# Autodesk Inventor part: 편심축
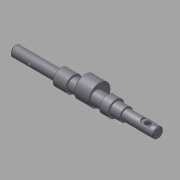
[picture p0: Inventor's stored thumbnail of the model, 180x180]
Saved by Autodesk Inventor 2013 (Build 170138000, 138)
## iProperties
Company: 한국ATC센터
Created: 2015-12
Part Number: 편심축
Document SubType Name: Modeling
Designer: mdu
Density: 7.86 g/cm^3
Mass: 248.518 g
Surface Area: 94.9944 cm^2
Volume: 31.6181 cm^3
Material: 강철, 연강
Author: mdu
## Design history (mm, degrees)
sketch "스케치1"
  geometry: L1 (-84.5, 0)-(84.5, 0); L2 (-84.5, 0)-(-84.5, 6); L3 (-84.5, 6)-(-30.5, 6); L4 (-30.5, 6)-(-30.5, 9.5); L5 (-30.5, 9.5)-(-15.5, 9.5); L6 (-15.5, 9.5)-(-15.5, 7.5); L7 (-15.5, 7.5)-(46.5, 7.5); L8 (84.5, 6)-(84.5, 0); L9 (34.5, 7.5)-(34.5, 9.5); L10 (34.5, 9.5)-(24.5, 9.5); L11 (24.5, 9.5)-(24.5, 7.5); L12 (46.5, 7.5)-(46.5, 6); L13 (46.5, 6)-(84.5, 6); 2 further points
  constraints: 26 end point, 6 parallel, 6 perpendicular, 2 point on line, 1 coincident, 1 horizontal, 1 midpoint
  dimensions: "d1" = 12 diameter of L3 L1; "d2" = 15 diameter of L7 L1; "d4" = 15 distance of L4.end L5.end; "d5" = 19 diameter of L5 L1; "d24" = 10 distance of L9.end L10.end; "d25" = 19 diameter of L10 L1; "d27" = 40 distance between parallel lines of L11 L6; "d28" = 54 distance of L2.end L3.end; "d29" = 50 distance between parallel lines of L8 L9; "d41" = 38 distance between parallel lines of L8 L12; "d42" = 12 diameter of L13 L1
revolve "회전1" stored, may be unused: angle "d6" = 90 deg
node "작업 평면1"
sketch "스케치2"
  geometry: C1 r 7.5 at (0, 0) reference; C2 r 12.5 at (0, 4.5); 1 further point
  constraints: 1 centre point, 1 vertical alignment
  dimensions: "d8" = 4.5 distance of point (0, 0) C2.centre; "d9" = 25 diameter of C2
extrude "돌출1" join sketch "스케치2" distance "d10" = 18; taper "d11" = 0 deg
chamfer "모따기1" distance "d12" = 1; stored, may be unused: second distance "d13" = 2, angle "d14" = 45 deg
chamfer "모따기2" distance "d15" = 0.5; stored, may be unused: second distance "d16" = 2, angle "d17" = 45 deg
node "작업 평면2"
sketch "스케치3"
  geometry: L1 (4, -2)-(18, -2); L2 (18, 2)-(4, 2); L3 (27, 5)-(27, -5) reference; A1 r 2 centre (18, 0) between (18, -2) and (18, 2); A2 r 2 centre (4, 0) between (4, 2) and (4, -2); 2 further points
  constraints: 4 end point, 4 point on circle, 4 tangent, 2 centre point, 1 horizontal, 1 horizontal alignment, 1 midpoint, 1 parallel
  dimensions: "d18" = 7 distance edge to line of A1 L3; "d19" = 4 distance between parallel lines of L2 L1; "d20" = 18 dimension on A1 A2
extrude "돌출2" cut sketch "스케치3" distance "d21" = 2.5; taper "d22" = 0 deg
revolve "회전2" stored, may be unused: angle "d26" = 90 deg
node "작업 평면3"
sketch "스케치4"
  geometry: L1 (44, 5)-(44, -5) reference; 2 further points
  constraints: 1 horizontal alignment
  dimensions: "d30" = 12 distance from line of point (32, 0) L1
hole "구멍1" sketch "스케치4" at (32, 0) diameter "d31" = 6; stored, may be unused: countersink angle "d35" = 90 deg, drill point angle "d37" = 118 deg; dims "d32" = 6, "d33" = 14, "d34" = 3, "d36" = 8
node "작업 평면4"
sketch "스케치5"
  geometry: C1 r 3 at (32, 0) reference; C2 r 8 at (32, 0); 2 further points
  constraints: 1 centre point, 1 coincident, 1 other
  dimensions: "d38" = 16 diameter of C2
extrude "돌출3" cut sketch "스케치5" distance "d39" = 3; taper "d40" = 0 deg
sketch "스케치6"
  geometry: L1 (-83.5, -6)-(-30.5, -6) reference; L2 (-84.5, -5)-(-84.5, 5) reference; L3 (-83.5, 6)-(-30.5, 6) reference; L4 (-62.5, 6)-(-62.5, -6); L5 (-62.5, -6)-(-61, -6); L6 (-62.5, -4.5)-(-61, -6); L7 (-62.5, -6)-(-62.5, -4.5); 2 further points
  constraints: 8 end point, 4 point on line, 2 perpendicular, 1 coincident
  dimensions: "d43" = 22 distance between parallel lines of L4 L2; "d44" = 45 deg angle of L6 L7; "d45" = 3 diameter of L5.end L4
revolve "회전3" stored, may be unused: angle "d46" = 90 deg
node "작업점1"
chamfer "모따기3" distance "d47" = 0.5; stored, may be unused: second distance "d48" = 2, angle "d49" = 45 deg
node "솔리드1"
node "투영된 루프1"
other parameters: "d7" = 8.5
